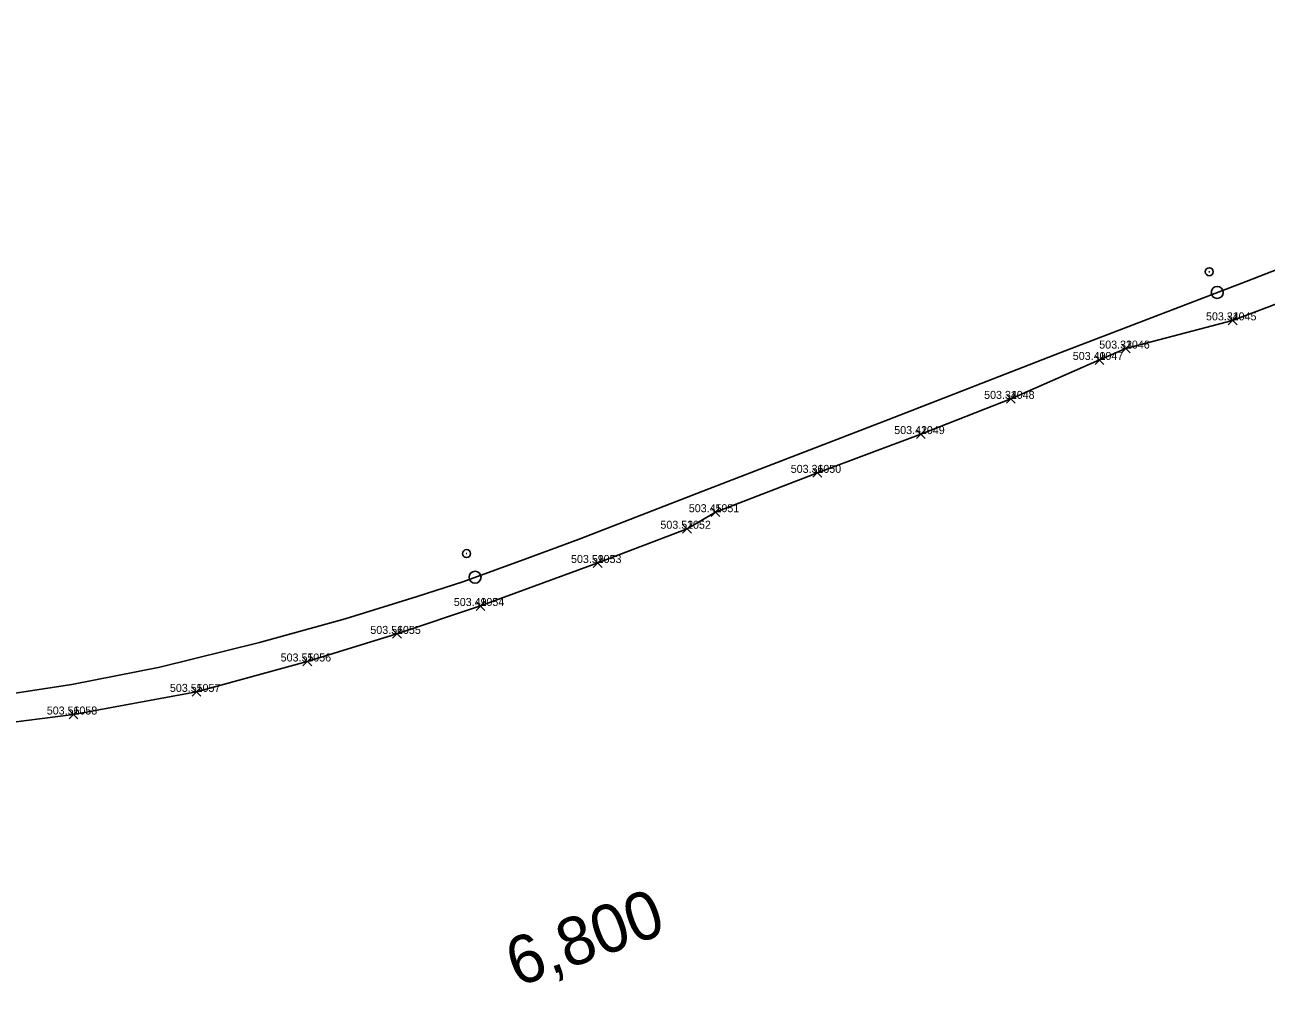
# Model space of a CAD drawing. Extents: x -874058 to -854960, y -10531873 to -1049126.
# Drawn here: x -870635 to -870479.8, y -1054401 to -1054281 of the extents above; entities that cross this region are included whole.
import ezdxf

# ---------------------------------------------------------------- set-up
doc = ezdxf.new("R2010")
doc.units = 0
for name, color, linetype in [('Vrstva 1', 7, 'Continuous'), ('Vrstva 32', 7, 'Continuous'), ('Vrstva 60', 7, 'Continuous'), ('Vrstva 61', 7, 'Continuous'), ('Vrstva 7', 7, 'Continuous')]:
    doc.layers.add(name, color=color, linetype=linetype)

msp = doc.modelspace()

# ---------------------------------------------------------------- linework, layer by layer
at = {"layer": 'Vrstva 1'}
msp.add_lwpolyline([(-870641.64, -1054365.38), (-870629.08, -1054363.48), (-870618.09, -1054361.31), (-870605.64, -1054358.24), (-870594.93, -1054355.28), (-870585.91, -1054352.49), (-870580.23, -1054350.62), (-870572.23, -1054347.71), (-870565.68, -1054345.3), (-870549.45, -1054338.99), (-870527.1, -1054330.39), (-870505.47, -1054321.95), (-870482.33, -1054313.07), (-870459.97, -1054304.38)], dxfattribs=at)
at = {"layer": 'Vrstva 32'}
msp.add_lwpolyline([(-870390.5, -1054280.98), (-870390.43, -1054281.96), (-870401.2, -1054285.37), (-870403.34, -1054286.23), (-870421.45, -1054293.58), (-870440.6, -1054301.19), (-870461.7, -1054309.51), (-870484, -1054317.94), (-870497.34, -1054321.47), (-870500.65, -1054322.89), (-870511.73, -1054327.76), (-870522.96, -1054332.16), (-870535.9, -1054337.01), (-870548.64, -1054341.93), (-870552.19, -1054344), (-870563.36, -1054348.28), (-870578.01, -1054353.66), (-870588.44, -1054357.15), (-870599.65, -1054360.6), (-870613.49, -1054364.4), (-870628.88, -1054367.23), (-870640.66, -1054368.74)], dxfattribs=at)
at = {"layer": 'Vrstva 60'}
for p, q in [((-870484.55, -1054318.49), (-870483.45, -1054317.39)), ((-870483.45, -1054318.49), (-870484.55, -1054317.39)), ((-870497.89, -1054322.02), (-870496.79, -1054320.92)), ((-870496.79, -1054322.02), (-870497.89, -1054320.92)), ((-870501.2, -1054323.44), (-870500.1, -1054322.34)), ((-870500.1, -1054323.44), (-870501.2, -1054322.34)), ((-870512.28, -1054328.31), (-870511.18, -1054327.21)), ((-870511.18, -1054328.31), (-870512.28, -1054327.21)), ((-870523.51, -1054332.71), (-870522.41, -1054331.61)), ((-870522.41, -1054332.71), (-870523.51, -1054331.61)), ((-870536.45, -1054337.56), (-870535.35, -1054336.46)), ((-870535.35, -1054337.56), (-870536.45, -1054336.46)), ((-870549.19, -1054342.48), (-870548.09, -1054341.38)), ((-870548.09, -1054342.48), (-870549.19, -1054341.38)), ((-870552.74, -1054344.55), (-870551.64, -1054343.45)), ((-870551.64, -1054344.55), (-870552.74, -1054343.45)), ((-870563.91, -1054348.83), (-870562.81, -1054347.73)), ((-870562.81, -1054348.83), (-870563.91, -1054347.73)), ((-870578.56, -1054354.21), (-870577.46, -1054353.11)), ((-870577.46, -1054354.21), (-870578.56, -1054353.11)), ((-870588.99, -1054357.7), (-870587.89, -1054356.6)), ((-870587.89, -1054357.7), (-870588.99, -1054356.6)), ((-870600.2, -1054361.15), (-870599.1, -1054360.05)), ((-870599.1, -1054361.15), (-870600.2, -1054360.05)), ((-870614.04, -1054364.95), (-870612.94, -1054363.85)), ((-870612.94, -1054364.95), (-870614.04, -1054363.85)), ((-870629.43, -1054367.78), (-870628.33, -1054366.68)), ((-870628.33, -1054367.78), (-870629.43, -1054366.68))]:
    msp.add_line(p, q, dxfattribs=at)
at = {"layer": 'Vrstva 7'}
for p, q in [((-870486.97, -1054311.87), (-870486.87, -1054311.87)), ((-870579.8, -1054347.11), (-870579.7, -1054347.11))]:
    msp.add_line(p, q, dxfattribs=at)
for centre, radius in [((-870486.92, -1054311.87), 0.5), ((-870485.93, -1054314.45), 0.75), ((-870579.75, -1054347.11), 0.5), ((-870578.68, -1054350.06), 0.75)]:
    msp.add_circle(centre, radius, dxfattribs=at)

# ---------------------------------------------------------------- texts
at = {"layer": 'Vrstva 60'}
for s, p in [('1045', (-870484, -1054317.94)), ('1046', (-870497.34, -1054321.47)), ('1047', (-870500.65, -1054322.89)), ('1048', (-870511.73, -1054327.76)), ('1049', (-870522.96, -1054332.16)), ('1050', (-870535.9, -1054337.01)), ('1051', (-870548.64, -1054341.93)), ('1052', (-870552.19, -1054344)), ('1053', (-870563.36, -1054348.28)), ('1054', (-870578.01, -1054353.66)), ('1055', (-870588.44, -1054357.15)), ('1056', (-870599.65, -1054360.6)), ('1057', (-870613.49, -1054364.4)), ('1058', (-870628.88, -1054367.23))]:
    msp.add_text(s, height=1, dxfattribs=at).set_placement(p)
at = {"layer": 'Vrstva 61'}
for s, p in [('503.34 ', (-870487.33, -1054317.94)), ('503.33 ', (-870500.67, -1054321.47)), ('503.40 ', (-870503.98, -1054322.89)), ('503.34 ', (-870515.06, -1054327.76)), ('503.42 ', (-870526.29, -1054332.16)), ('503.36 ', (-870539.23, -1054337.01)), ('503.45 ', (-870551.97, -1054341.93)), ('503.52 ', (-870555.52, -1054344)), ('503.59 ', (-870566.69, -1054348.28)), ('503.49 ', (-870581.34, -1054353.66)), ('503.56 ', (-870591.77, -1054357.15)), ('503.55 ', (-870602.98, -1054360.6)), ('503.55 ', (-870616.82, -1054364.4)), ('503.56 ', (-870632.21, -1054367.23))]:
    msp.add_text(s, height=1, dxfattribs=at).set_placement(p)
at = {"layer": 'Vrstva 7'}
msp.add_text('6,800', height=6, rotation=19.9889, dxfattribs=at).set_placement((-870573.43, -1054401.35))

doc.saveas('drawing.dxf')
